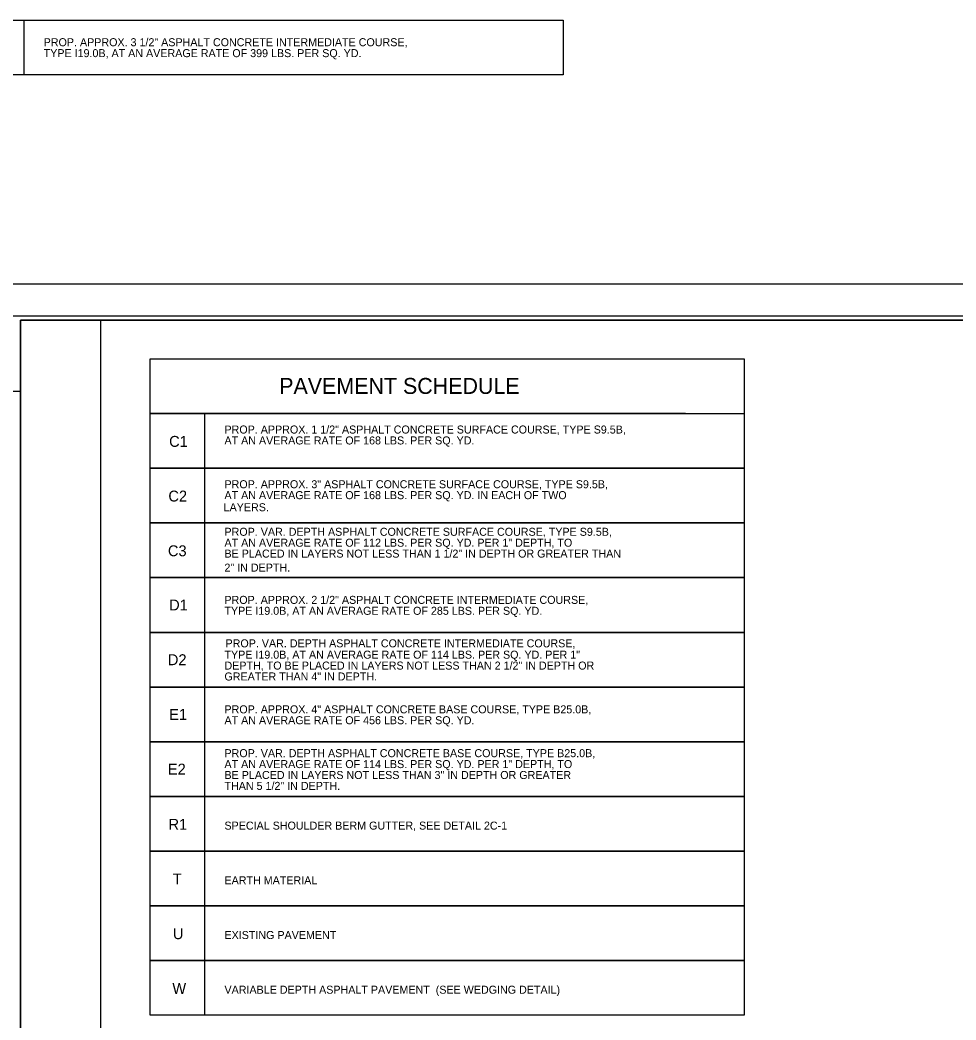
# Model space of a CAD drawing. Extents: x 1593595 to 1594166, y 741647 to 741854.
# Drawn here: x 1593959.3 to 1594029.4, y 741779.1 to 741854.1 of the extents above; entities that cross this region are included whole.
import ezdxf

# ---------------------------------------------------------------- set-up
doc = ezdxf.new("R2010")
doc.units = 0
for name, color, linetype in [('Default', 7, 'Continuous'), ('Prop Pavement Schedule Description CELL', 7, 'Continuous'), ('Sheet Block Revision CELL', 7, 'Continuous'), ('Sheet Clip Boundary CELL', 7, 'Continuous'), ('Sheet Cutting Line CELL', 7, 'Continuous'), ('Sheet Layout Plan Border', 7, 'Continuous'), ('Sheet Plan CELL', 7, 'Continuous'), ('Sheet Plan Layout CELL', 7, 'Continuous'), ('Sheet Plot Border Inside CELL', 7, 'Continuous'), ('Sheet Plot Border Outside CELL', 7, 'Continuous')]:
    doc.layers.add(name, color=color, linetype=linetype)

msp = doc.modelspace()

# ---------------------------------------------------------------- linework, layer by layer
at = {"layer": 'Default'}
for points in [[(1593959.596, 741849.957), (1593955.496, 741849.957), (1593955.496, 741854.057), (1593999.981, 741854.057), (1593999.981, 741849.957), (1593959.596, 741849.957), (1593959.596, 741854.057)], [(1593973.136, 741808.157), (1593969.036, 741808.157), (1593969.036, 741812.257), (1594013.521, 741812.257), (1594013.521, 741808.157), (1593973.136, 741808.157), (1593973.136, 741812.257)]]:
    msp.add_lwpolyline(points, dxfattribs=at)
at = {"layer": 'Prop Pavement Schedule Description CELL'}
for p, q in [((1593969.036, 741824.56), (1593969.036, 741828.66)), ((1593969.036, 741828.66), (1594013.521, 741828.66)), ((1594013.521, 741828.66), (1594013.521, 741824.56)), ((1593973.136, 741824.56), (1593969.036, 741824.56)), ((1594009.127, 741824.56), (1593973.136, 741824.56)), ((1593973.136, 741820.459), (1593969.036, 741820.459)), ((1594009.127, 741820.459), (1593973.136, 741820.459))]:
    msp.add_line(p, q, dxfattribs=at)
for points in [[(1593973.136, 741820.459), (1593969.036, 741820.459), (1593969.036, 741824.56), (1594013.521, 741824.56), (1594013.521, 741820.459), (1593973.136, 741820.459), (1593973.136, 741824.56)], [(1593973.136, 741816.358), (1593969.036, 741816.358), (1593969.036, 741820.459), (1594013.521, 741820.459), (1594013.521, 741816.358), (1593973.136, 741816.358), (1593973.136, 741820.459)], [(1593973.136, 741812.257), (1593969.036, 741812.257), (1593969.036, 741816.358), (1594013.521, 741816.358), (1594013.521, 741812.257), (1593973.136, 741812.257), (1593973.136, 741816.358)], [(1593973.136, 741804.056), (1593969.036, 741804.056), (1593969.036, 741808.157), (1594013.521, 741808.157), (1594013.521, 741804.056), (1593973.136, 741804.056), (1593973.136, 741808.157)], [(1593973.136, 741799.956), (1593969.036, 741799.956), (1593969.036, 741804.056), (1594013.521, 741804.056), (1594013.521, 741799.956), (1593973.136, 741799.956), (1593973.136, 741804.056)], [(1593973.136, 741795.856), (1593969.036, 741795.856), (1593969.036, 741799.956), (1594013.521, 741799.956), (1594013.521, 741795.856), (1593973.136, 741795.856), (1593973.136, 741799.956)], [(1593973.136, 741791.756), (1593969.036, 741791.756), (1593969.036, 741795.856), (1594013.521, 741795.856), (1594013.521, 741791.756), (1593973.136, 741791.756), (1593973.136, 741795.856)], [(1593973.136, 741787.656), (1593969.036, 741787.656), (1593969.036, 741791.756), (1594013.521, 741791.756), (1594013.521, 741787.656), (1593973.136, 741787.656), (1593973.136, 741791.756)], [(1593973.136, 741783.556), (1593969.036, 741783.556), (1593969.036, 741787.656), (1594013.521, 741787.656), (1594013.521, 741783.556), (1593973.136, 741783.556), (1593973.136, 741787.656)], [(1593973.136, 741779.455), (1593969.036, 741779.455), (1593969.036, 741783.556), (1594013.521, 741783.556), (1594013.521, 741779.455), (1593973.136, 741779.455), (1593973.136, 741783.556)]]:
    msp.add_lwpolyline(points, dxfattribs=at)
at = {"layer": 'Sheet Block Revision CELL'}
msp.add_lwpolyline([(1593952.053, 741731.357), (1593952.053, 741826.235), (1593959.318, 741826.238), (1593959.318, 741731.36)], close=True, dxfattribs=at)
at = {"layer": 'Sheet Clip Boundary CELL'}
msp.add_lwpolyline([(1593965.316, 741705.56), (1594133.318, 741705.56), (1594133.318, 741806.182), (1594110.606, 741806.182), (1594110.606, 741831.56), (1593965.316, 741831.56)], close=True, dxfattribs=at)
at = {"layer": 'Sheet Cutting Line CELL'}
msp.add_line((1594141.358, 741834.259), (1593939.338, 741834.259), dxfattribs=at)
at = {"layer": 'Sheet Layout Plan Border'}
msp.add_lwpolyline([(1593965.316, 741705.56), (1594133.318, 741705.56), (1594133.318, 741806.182), (1594110.606, 741806.182), (1594110.606, 741831.56), (1593965.316, 741831.56)], close=True, dxfattribs=at)
at = {"layer": 'Sheet Plan CELL'}
msp.add_line((1593959.316, 741831.56), (1593959.316, 741831.56), dxfattribs=at)
for points in [[(1593959.316, 741705.56), (1593959.313, 741831.557), (1594115.312, 741831.562), (1594115.313, 741813.554), (1594139.318, 741813.553), (1594139.318, 741705.56)], [(1594139.321, 741831.56), (1593959.316, 741831.56), (1593959.316, 741705.56), (1594139.318, 741705.56)]]:
    msp.add_lwpolyline(points, close=True, dxfattribs=at)
at = {"layer": 'Sheet Plan Layout CELL'}
msp.add_lwpolyline([(1593959.313, 741831.557), (1593959.316, 741705.56), (1594139.316, 741705.56), (1594139.316, 741806.182), (1594110.606, 741806.182), (1594110.606, 741831.56)], close=True, dxfattribs=at)
at = {"layer": 'Sheet Plot Border Inside CELL'}
msp.add_lwpolyline([(1593940.898, 741705.259), (1594140.816, 741705.26), (1594140.818, 741831.859), (1593940.898, 741831.859)], close=True, dxfattribs=at)
at = {"layer": 'Sheet Plot Border Outside CELL'}
msp.add_lwpolyline([(1593939.338, 741702.859), (1594141.358, 741702.859), (1594141.358, 741834.259), (1593939.338, 741834.259)], close=True, dxfattribs=at)

# ---------------------------------------------------------------- texts
at = {"layer": 'Default'}
for s, p in [('PROP. VAR. DEPTH ASPHALT CONCRETE SURFACE COURSE, TYPE S9.5B,', (1593974.598, 741815.395)), ('AT AN AVERAGE RATE OF 112 LBS. PER SQ. YD. PER 1" DEPTH, TO', (1593974.598, 741814.577)), ('BE PLACED IN LAYERS NOT LESS THAN 1 1/2" IN DEPTH OR GREATER THAN', (1593974.598, 741813.76)), ('2" IN DEPTH.', (1593974.598, 741812.71))]:
    msp.add_text(s, height=0.60001, dxfattribs=at).set_placement(p)
at = {"layer": 'Prop Pavement Schedule Description CELL'}
for s, height, p in [('PROP. APPROX. 3 1/2" ASPHALT CONCRETE INTERMEDIATE COURSE,', 0.60001, (1593961.053, 741852.091)), ('TYPE I19.0B, AT AN AVERAGE RATE OF 399 LBS. PER SQ. YD.', 0.60001, (1593961.053, 741851.273)), ('PAVEMENT SCHEDULE', 1.20002, (1593978.699, 741826.028)), ('PROP. APPROX. 1 1/2" ASPHALT CONCRETE SURFACE COURSE, TYPE S9.5B, ', 0.60001, (1593974.598, 741823.06)), ('C1', 0.8185, (1593970.453, 741822.062)), ('AT AN AVERAGE RATE OF 168 LBS. PER SQ. YD. ', 0.60001, (1593974.598, 741822.242)), ('PROP. APPROX. 3" ASPHALT CONCRETE SURFACE COURSE, TYPE S9.5B, ', 0.60001, (1593974.598, 741818.959)), ('C2', 0.8185, (1593970.396, 741817.961)), ('AT AN AVERAGE RATE OF 168 LBS. PER SQ. YD. IN EACH OF TWO', 0.60001, (1593974.598, 741818.141)), ('LAYERS.', 0.6, (1593974.535, 741817.234)), ('C3', 0.8185, (1593970.363, 741813.86)), ('D1', 0.8185, (1593970.453, 741809.798)), ('PROP. APPROX. 2 1/2" ASPHALT CONCRETE INTERMEDIATE COURSE,', 0.60001, (1593974.594, 741810.291)), ('TYPE I19.0B, AT AN AVERAGE RATE OF 285 LBS. PER SQ. YD.', 0.60001, (1593974.594, 741809.473)), ('PROP. VAR. DEPTH ASPHALT CONCRETE INTERMEDIATE COURSE,', 0.60001, (1593974.678, 741807.033)), ('TYPE I19.0B, AT AN AVERAGE RATE OF 114 LBS. PER SQ. YD. PER 1" ', 0.60001, (1593974.598, 741806.183)), ('D2', 0.8185, (1593970.358, 741805.697)), ('DEPTH, TO BE PLACED IN LAYERS NOT LESS THAN 2 1/2" IN DEPTH OR', 0.60001, (1593974.598, 741805.366)), ('GREATER THAN 4" IN DEPTH.', 0.60001, (1593974.598, 741804.548)), ('E1', 0.8185, (1593970.453, 741801.596)), ('PROP. APPROX. 4" ASPHALT CONCRETE BASE COURSE, TYPE B25.0B,', 0.60001, (1593974.598, 741802.086)), ('AT AN AVERAGE RATE OF 456 LBS. PER SQ. YD.', 0.60001, (1593974.598, 741801.269)), ('PROP. VAR. DEPTH ASPHALT CONCRETE BASE COURSE, TYPE B25.0B,', 0.60001, (1593974.598, 741798.801)), ('AT AN AVERAGE RATE OF 114 LBS. PER SQ. YD. PER 1" DEPTH, TO', 0.60001, (1593974.598, 741797.983)), ('E2', 0.8185, (1593970.358, 741797.496)), ('BE PLACED IN LAYERS NOT LESS THAN 3" IN DEPTH OR GREATER', 0.60001, (1593974.598, 741797.165)), ('THAN 5 1/2" IN DEPTH.', 0.60001, (1593974.598, 741796.348)), ('R1', 0.8185, (1593970.407, 741793.359)), ('SPECIAL SHOULDER BERM GUTTER, SEE DETAIL 2C-1', 0.60001, (1593974.598, 741793.371)), ('T', 0.819, (1593970.725, 741789.259)), ('EARTH MATERIAL', 0.60001, (1593974.598, 741789.27)), ('U', 0.819, (1593970.736, 741785.158)), ('EXISTING PAVEMENT', 0.60001, (1593974.598, 741785.17)), ('W', 0.819, (1593970.694, 741781.058)), ('VARIABLE DEPTH ASPHALT PAVEMENT  (SEE WEDGING DETAIL)', 0.60001, (1593974.598, 741781.07))]:
    msp.add_text(s, height=height, dxfattribs=at).set_placement(p)

doc.saveas('drawing.dxf')
